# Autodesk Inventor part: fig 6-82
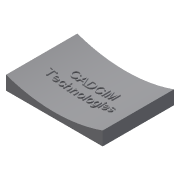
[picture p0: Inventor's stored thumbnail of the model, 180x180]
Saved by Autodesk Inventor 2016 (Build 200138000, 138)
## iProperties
Shininess: 64.0
Length Units: 11269
Angle Units: 11279
Time Units: 11290
Mass Units: 11283
Length Display Precision: 3
Angle Display Precision: 2
Compacted: True
Part Number: fig 6-82
Document SubType Name: Modeling
Created: 2002-12
Designer: deepak
Density: 1 g/cm^3
Material: Generic
Appearance: Default
Density: 0.0
Volumn: 0.0
Area: 0.0
PropertySet Name: Model Information
Control State: 0
Master: False
Checked Out: False
Author: deepak
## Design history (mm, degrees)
sketch "Sketch1"
  geometry: L1 (-39.922, 33.786)-(30.103, 33.786); L2 (30.103, 33.786)-(30.103, -17.894); L3 (30.103, -17.894)-(-39.922, -17.894); L4 (-39.922, -17.894)-(-39.922, 33.786)
  constraints: 8 end point, 2 parallel, 1 horizontal, 1 perpendicular
extrude "Extrusion1" new body sketch "Sketch1" distance "d0" = 10; taper "d1" = 0 deg
workplane "Work Plane1"
sketch "Sketch2"
  geometry: L1 (-37.656, 15.034)-(26.28, 15.034); L2 (26.28, 15.034)-(26.28, 10.168); L3 (26.28, 10.168)-(-37.656, 10.168); L4 (-37.656, 10.168)-(-37.656, 15.034)
  constraints: 2 other
sketch "Sketch3"
  geometry: L1 (70.026, 10)-(0, 10) reference; A1 r 105 centre (35.013, 108.99) between (0, 10) and (70.026, 10)
  constraints: 2 point on circle, 1 centre point
  dimensions: "d5" = 105 radius of A1
extrude "Extrusion2" cut sketch "Sketch3" stored distance "d3" = 10; taper "d4" = 0 deg
emboss "Emboss4" sketch "Sketch2" dims "d14" = 1, "d15" = 0
body "Solid1"
other parameters: "d2" = 5
